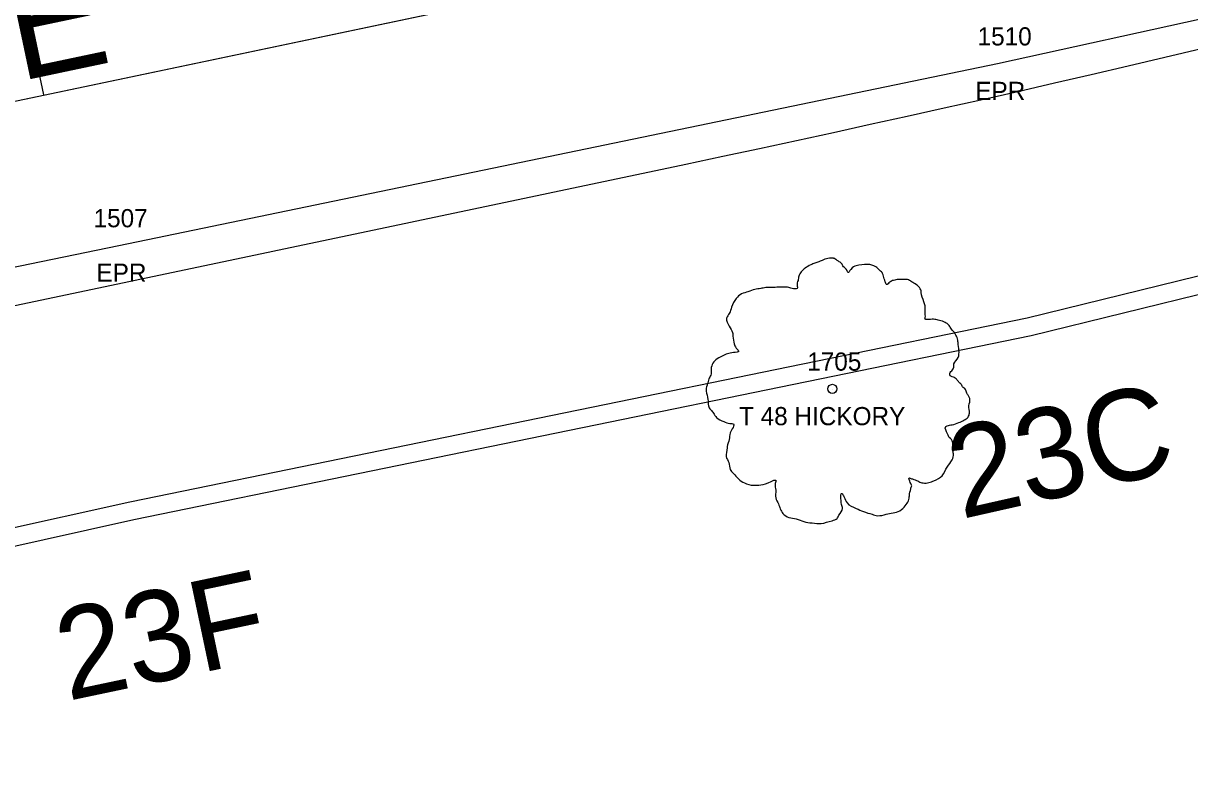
# Model space of a CAD drawing. Extents: x 1964982 to 1970452, y 1116335 to 1119906.
# Drawn here: x 1966576 to 1966640.1, y 1117362.4 to 1117403.2 of the extents above; entities that cross this region are included whole.
import ezdxf

# ---------------------------------------------------------------- set-up
doc = ezdxf.new("R2010")
doc.units = 0
for name, color, linetype in [('RD_EX_DV_Prop', 7, 'Continuous'), ('RD_EX_Road', 7, 'Continuous'), ('RD_EX_Road_txCode', 7, 'Continuous'), ('RD_EX_RW', 7, 'Continuous'), ('RD_EX_VEG', 7, 'Continuous'), ('RD_EX_VEG_txCode', 7, 'Continuous'), ('RD_HC_CL', 7, 'Continuous'), ('RD_HC_Data', 7, 'Continuous'), ('RD_HC_Data_Tic', 7, 'Continuous'), ('RD_PD_CstnLmt', 7, 'Continuous'), ('RD_PD_Final_TrvlWay', 7, 'Continuous'), ('RD_PD_RW', 7, 'Continuous'), ('RD_PD_TX_CstnLmt', 7, 'Continuous'), ('RD_SMD_Locator', 7, 'Continuous')]:
    doc.layers.add(name, color=color, linetype=linetype)

msp = doc.modelspace()

# ---------------------------------------------------------------- linework, layer by layer
at = {"layer": 'RD_EX_DV_Prop'}
msp.add_line((1966425.261, 1117367.215), (1966684.872, 1117421.945), dxfattribs=at)
at = {"layer": 'RD_EX_Road'}
msp.add_lwpolyline([(1965729.992, 1117080.297), (1965819.77, 1117119.134), (1965907.737, 1117159.312), (1965995.365, 1117199.039), (1966039.268, 1117218.497), (1966081.241, 1117237.148), (1966124.665, 1117256.555), (1966167.659, 1117275.555), (1966211.467, 1117293.627), (1966257.791, 1117311.581), (1966302.7, 1117327.207), (1966347.903, 1117339.982), (1966394.806, 1117351.637), (1966441.557, 1117361.865), (1966488.625, 1117372.057), (1966534.906, 1117381.34), (1966581.234, 1117390.947), (1966629.533, 1117400.947), (1966675.632, 1117411.107), (1966721.676, 1117422.847), (1966766.802, 1117438.972), (1966775.751, 1117440.571)], dxfattribs=at)
at = {"layer": 'RD_EX_RW'}
msp.add_lwpolyline([(1965729.992, 1117080.297), (1965819.77, 1117119.134), (1965907.737, 1117159.312), (1965995.365, 1117199.039), (1966039.268, 1117218.497), (1966081.241, 1117237.148), (1966124.665, 1117256.555), (1966167.659, 1117275.555), (1966211.467, 1117293.627), (1966257.791, 1117311.581), (1966302.7, 1117327.207), (1966347.903, 1117339.982), (1966394.806, 1117351.637), (1966441.557, 1117361.865), (1966488.625, 1117372.057), (1966534.906, 1117381.34), (1966581.234, 1117390.947), (1966629.533, 1117400.947), (1966675.632, 1117411.107), (1966721.676, 1117422.847), (1966766.802, 1117438.972), (1966775.751, 1117440.571)], dxfattribs=at)
at = {"layer": 'RD_EX_VEG'}
for centre, radius in [((1966620.454, 1117383.059), 0.25), ((1966620.441, 1117383.04), 0.0001)]:
    msp.add_circle(centre, radius, dxfattribs=at)
for points in [[(1966620.586, 1117390.226), (1966620.286, 1117390.251), (1966619.961, 1117390.151), (1966619.711, 1117390.052), (1966619.486, 1117389.977), (1966619.261, 1117389.877), (1966618.961, 1117389.702), (1966618.737, 1117389.502), (1966618.612, 1117389.252), (1966618.562, 1117389.027), (1966618.512, 1117388.752), (1966618.512, 1117388.577), (1966618.387, 1117388.552), (1966618.237, 1117388.577), (1966617.987, 1117388.652), (1966617.737, 1117388.652), (1966617.487, 1117388.652), (1966617.137, 1117388.627), (1966616.787, 1117388.627), (1966616.513, 1117388.577), (1966616.188, 1117388.527), (1966615.813, 1117388.402), (1966615.463, 1117388.277), (1966615.163, 1117388.027), (1966614.913, 1117387.553), (1966614.788, 1117387.203), (1966614.638, 1117386.953), (1966614.788, 1117386.503), (1966614.963, 1117386.153), (1966614.988, 1117385.953), (1966615.063, 1117385.529), (1966615.163, 1117385.304), (1966615.288, 1117385.104), (1966615.213, 1117385.079), (1966614.838, 1117385.029), (1966614.538, 1117384.929), (1966614.114, 1117384.704), (1966613.889, 1117384.479), (1966613.789, 1117384.154), (1966613.764, 1117383.804), (1966613.664, 1117383.604), (1966613.589, 1117383.329), (1966613.564, 1117383.254), (1966613.514, 1117382.93), (1966613.614, 1117382.48), (1966613.639, 1117382.13), (1966613.764, 1117381.905), (1966613.914, 1117381.73), (1966614.089, 1117381.48), (1966614.488, 1117381.255), (1966614.813, 1117381.155), (1966615.013, 1117381.13), (1966614.838, 1117380.631), (1966614.788, 1117380.281), (1966614.663, 1117379.881), (1966614.663, 1117379.806), (1966614.613, 1117379.331), (1966614.763, 1117379.006), (1966614.838, 1117378.632), (1966615.013, 1117378.407), (1966615.288, 1117378.107), (1966615.613, 1117377.882), (1966616.113, 1117377.757), (1966616.513, 1117377.782), (1966617.087, 1117377.957), (1966617.337, 1117378.032), (1966617.312, 1117377.857), (1966617.337, 1117377.482), (1966617.337, 1117377.057), (1966617.487, 1117376.732), (1966617.587, 1117376.457), (1966617.737, 1117376.208), (1966618.062, 1117375.983), (1966618.462, 1117375.908), (1966618.886, 1117375.758), (1966619.336, 1117375.683), (1966619.836, 1117375.658), (1966620.436, 1117375.808), (1966620.711, 1117375.933), (1966620.811, 1117376.108), (1966621.011, 1117376.482), (1966620.961, 1117376.707), (1966620.986, 1117377.307), (1966621.085, 1117377.132), (1966621.26, 1117376.782), (1966621.76, 1117376.482), (1966622.16, 1117376.308), (1966622.635, 1117376.158), (1966622.935, 1117376.083), (1966623.409, 1117376.158), (1966623.784, 1117376.233), (1966624.159, 1117376.358), (1966624.459, 1117376.632), (1966624.634, 1117376.907), (1966624.684, 1117377.182), (1966624.759, 1117377.557), (1966624.809, 1117377.732)], [(1966624.809, 1117377.732), (1966624.734, 1117377.907), (1966624.684, 1117378.157), (1966624.759, 1117378.132), (1966624.934, 1117378.082), (1966625.209, 1117377.957), (1966625.434, 1117377.882), (1966625.758, 1117377.907), (1966626.033, 1117378.007), (1966626.483, 1117378.282), (1966626.758, 1117378.756), (1966627.033, 1117379.156), (1966627.108, 1117379.481), (1966627.058, 1117379.706), (1966627.033, 1117380.206), (1966626.833, 1117380.456), (1966626.783, 1117380.581), (1966626.683, 1117380.98), (1966626.758, 1117381.03), (1966627.033, 1117381.08), (1966627.408, 1117381.205), (1966627.683, 1117381.33), (1966627.908, 1117381.505), (1966627.982, 1117381.73), (1966627.958, 1117382.13), (1966628.007, 1117382.53), (1966627.933, 1117382.68), (1966627.833, 1117382.83), (1966627.758, 1117383.03), (1966627.608, 1117383.179), (1966627.508, 1117383.329), (1966627.408, 1117383.429), (1966627.283, 1117383.579), (1966627.108, 1117383.704), (1966626.958, 1117383.754), (1966626.908, 1117383.904), (1966627.058, 1117384.104), (1966627.108, 1117384.204), (1966627.133, 1117384.429), (1966627.358, 1117384.779), (1966627.408, 1117385.179), (1966627.358, 1117385.603), (1966627.308, 1117385.878), (1966627.158, 1117386.153), (1966626.958, 1117386.403), (1966626.833, 1117386.578), (1966626.658, 1117386.703), (1966626.333, 1117386.828), (1966626.083, 1117386.878), (1966625.733, 1117386.878), (1966625.534, 1117386.928), (1966625.559, 1117386.978), (1966625.559, 1117387.128), (1966625.559, 1117387.403), (1966625.484, 1117387.852), (1966625.334, 1117388.352), (1966625.334, 1117388.377), (1966625.234, 1117388.627), (1966625.009, 1117388.827), (1966624.834, 1117388.927), (1966624.634, 1117389.052), (1966624.384, 1117389.077), (1966624.084, 1117389.077), (1966623.809, 1117389.027), (1966623.609, 1117388.927), (1966623.434, 1117388.802), (1966623.359, 1117388.952), (1966623.26, 1117389.252), (1966623.21, 1117389.402), (1966623.06, 1117389.577), (1966622.835, 1117389.777), (1966622.385, 1117389.902), (1966621.76, 1117389.827), (1966621.46, 1117389.627), (1966621.31, 1117389.452), (1966621.26, 1117389.577), (1966621.06, 1117389.777), (1966620.961, 1117389.952), (1966620.786, 1117390.077), (1966620.636, 1117390.176), (1966620.536, 1117390.226)]]:
    msp.add_spline(points, degree=3, dxfattribs=at)
at = {"layer": 'RD_HC_CL'}
msp.add_line((1966425.261, 1117367.215), (1966684.871, 1117421.945), dxfattribs=at)
at = {"layer": 'RD_HC_Data_Tic'}
msp.add_line((1966577.124, 1117399.23), (1966576.299, 1117403.144), dxfattribs=at)
at = {"layer": 'RD_PD_CstnLmt'}
for p, q in [((1966680.687, 1117399.137), (1966631.148, 1117386.955)), ((1966631.148, 1117386.955), (1966581.847, 1117376.829)), ((1966581.847, 1117376.829), (1966533.041, 1117365.953))]:
    msp.add_line(p, q, dxfattribs=at)
at = {"layer": 'RD_PD_Final_TrvlWay'}
msp.add_line((1966427.53, 1117356.451), (1966612.394, 1117395.424), dxfattribs=at)
msp.add_arc((1966373.74, 1118527.456), 1156.915, 281.904723, 295.046328, dxfattribs=at)
at = {"layer": 'RD_PD_RW'}
for p, q in [((1966680.946, 1117398.171), (1966631.369, 1117385.979)), ((1966631.369, 1117385.979), (1966582.056, 1117375.851)), ((1966582.056, 1117375.851), (1966533.265, 1117364.979))]:
    msp.add_line(p, q, dxfattribs=at)
at = {"layer": 'RD_SMD_Locator'}
for centre in [(1966629.533, 1117400.947), (1966629.533, 1117400.947), (1966581.234, 1117390.947), (1966581.234, 1117390.947)]:
    msp.add_circle(centre, 0.001, dxfattribs=at)

# ---------------------------------------------------------------- texts
at = {"layer": 'RD_EX_Road_txCode'}
for s, p in [('1510', (1966628.43, 1117401.947)), ('1510', (1966628.43, 1117401.947)), ('EPR', (1966628.304, 1117398.947)), ('EPR', (1966628.304, 1117398.947)), ('1507', (1966579.848, 1117391.947)), ('1507', (1966579.848, 1117391.947)), ('EPR', (1966580.006, 1117388.947)), ('EPR', (1966580.006, 1117388.947))]:
    msp.add_text(s, height=1, dxfattribs=at).set_placement(p)
at = {"layer": 'RD_EX_VEG_txCode'}
for s, p in [('1705', (1966619.068, 1117384.059)), ('T 48 HICKORY', (1966615.32, 1117381.059))]:
    msp.add_text(s, height=1, dxfattribs=at).set_placement(p)
at = {"layer": 'RD_HC_Data'}
msp.add_text('N 78° 05\' 43" E', height=6, rotation=11.90472, dxfattribs=at).set_placement((1966527.716, 1117389.836))
at = {"layer": 'RD_PD_TX_CstnLmt'}
for s, rotation, p in [('23C', 12.71843, (1966627.528, 1117375.886)), ('23F', 11.90472, (1966578.419, 1117365.886))]:
    msp.add_text(s, height=5, rotation=rotation, dxfattribs=at).set_placement(p)

doc.saveas('drawing.dxf')
